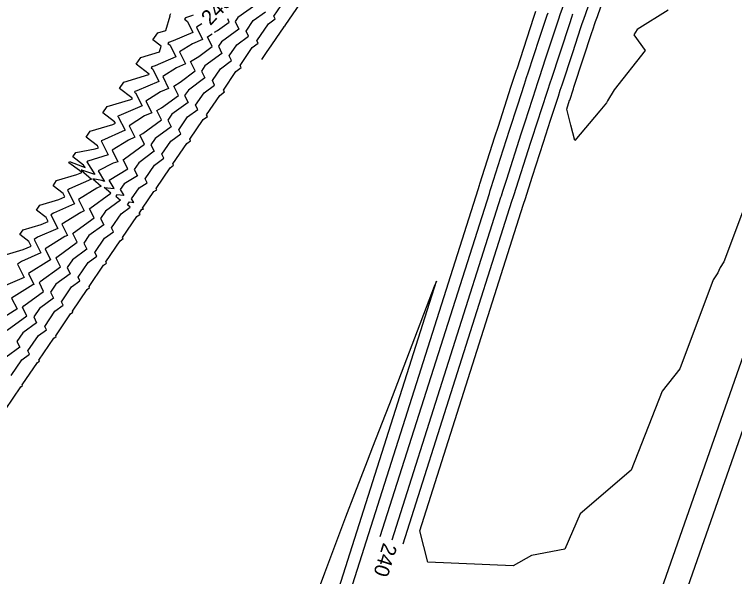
# Model space of a CAD drawing. Extents: x 1160447 to 1162032, y 616022 to 618272.
# Drawn here: x 1160877.4 to 1160997.8, y 616560 to 616654 of the extents above; entities that cross this region are included whole.
import ezdxf

# ---------------------------------------------------------------- set-up
doc = ezdxf.new("R2010")
doc.units = 0
doc.layers.add('D_Contours_Major', color=7, linetype='Continuous')
doc.layers.add('D_Contours_Minor', color=7, linetype='Continuous')

msp = doc.modelspace()

# ---------------------------------------------------------------- linework, layer by layer
at = {"layer": 'D_Contours_Major'}
for points in [[(1160969.77, 616657.13), (1160968.64, 616653.87), (1160968.38, 616653.13), (1160966.19, 616646.45), (1160965.24, 616643.54), (1160964.79, 616642.17), (1160964.61, 616641.62), (1160962.76, 616635.91), (1160962.12, 616633.94), (1160959.69, 616626.37), (1160959.04, 616624.33), (1160958.79, 616623.55), (1160958.73, 616623.36), (1160940.52, 616566.06)], [(1160925.19, 616655.85), (1160922.62, 616652.09), (1160922.66, 616652.01), (1160922.48, 616651.88), (1160919.81, 616647.97), (1160919.82, 616647.94), (1160919.77, 616647.91), (1160918.73, 616646.39)], [(1160908.78, 616652.36), (1160907.88, 616651.81), (1160908.9, 616649.76), (1160907.23, 616649.04), (1160905.05, 616647.69), (1160906.06, 616645.68), (1160904.54, 616645.02), (1160902.22, 616643.57), (1160903.22, 616641.59), (1160901.86, 616641), (1160899.4, 616639.46), (1160900.39, 616637.5), (1160899.19, 616636.98), (1160896.59, 616635.34), (1160897.56, 616633.41), (1160896.52, 616632.95), (1160893.78, 616631.23), (1160894.74, 616629.31), (1160893.94, 616629.06), (1160891.42, 616627.78), (1160892.49, 616626.03), (1160892.04, 616626.18), (1160890.53, 616626.46), (1160891.93, 616625.21), (1160891.19, 616624.89), (1160888.17, 616623), (1160889.12, 616621.11), (1160888.52, 616620.85), (1160885.37, 616618.88), (1160886.3, 616617.01), (1160885.86, 616616.81), (1160882.56, 616614.76), (1160883.49, 616612.91), (1160883.18, 616612.77), (1160879.76, 616610.65), (1160880.69, 616608.8), (1160880.5, 616608.73), (1160876.97, 616606.53), (1160877.88, 616604.7), (1160877.82, 616604.68), (1160874.17, 616602.41)], [(1160974.68, 616514.45), (1161006.96, 616606.59), (1161007.29, 616607.53), (1161007.74, 616608.8), (1161010.59, 616616.88), (1161011.09, 616618.29), (1161013.25, 616624.34), (1161013.42, 616624.81), (1161013.92, 616626.21), (1161014.8, 616628.63), (1161017.28, 616635.52), (1161017.6, 616638.61), (1161019.75, 616644.29), (1161020.92, 616644.74), (1161021.22, 616647.76), (1161021.25, 616647.83)]]:
    msp.add_lwpolyline(points, dxfattribs=at)
at = {"layer": 'D_Contours_Minor'}
for points in [[(1160986.75, 616654.67), (1160981.58, 616651.45), (1160980.98, 616650.53), (1160982.88, 616647.91), (1160977.73, 616641.35), (1160976.62, 616639.49), (1160976.43, 616639.17), (1160975.29, 616637.82), (1160971.11, 616632.88), (1160970.47, 616635.41), (1160969.78, 616638.13), (1160970.26, 616639.61), (1160970.27, 616639.63), (1160970.89, 616641.53), (1160970.97, 616641.77), (1160974.03, 616651.1), (1160974.06, 616651.2), (1160974.6, 616652.75), (1160974.9, 616653.6), (1160977.33, 616660.61)], [(1160999.14, 616620.91), (1160996.06, 616612.6), (1160995.44, 616611.66), (1160995.37, 616611.55), (1160995.06, 616610.73), (1160994.29, 616609.56), (1160988.7, 616594.7), (1160985.72, 616590.96), (1160980.56, 616577.76), (1160972.01, 616570.44), (1160969.44, 616564.53), (1160963.9, 616563.5), (1160960.8, 616561.74), (1160946.57, 616562.38), (1160945.2, 616567.59), (1160962.51, 616622.05), (1160962.63, 616622.41), (1160962.82, 616623.01), (1160964.07, 616626.93), (1160965.89, 616632.61), (1160967.08, 616636.27), (1160968.38, 616640.28), (1160968.7, 616641.26), (1160969, 616642.2), (1160970.78, 616647.59), (1160972.15, 616651.77), (1160972.38, 616652.43), (1160972.62, 616653.13), (1160974.41, 616658.31)], [(1160875.95, 616587.9), (1160878.51, 616591.66), (1160878.81, 616591.88), (1160878.74, 616592.01), (1160881.27, 616595.74), (1160881.61, 616595.98), (1160881.53, 616596.12), (1160884.04, 616599.81), (1160884.41, 616600.08), (1160884.33, 616600.23), (1160886.81, 616603.88), (1160887.21, 616604.17), (1160887.12, 616604.34), (1160889.58, 616607.95), (1160890.01, 616608.27), (1160889.92, 616608.45), (1160892.35, 616612.03), (1160892.82, 616612.36), (1160892.72, 616612.56), (1160895.13, 616616.1), (1160895.62, 616616.46), (1160895.52, 616616.66), (1160897.91, 616620.17), (1160898.43, 616620.55), (1160898.27, 616620.69), (1160898.74, 616621.39), (1160898.99, 616621.37), (1160898.87, 616621.57), (1160900.76, 616624.34), (1160901.24, 616624.64), (1160901.12, 616624.87), (1160903.47, 616628.3), (1160904.05, 616628.73), (1160903.93, 616628.97), (1160906.25, 616632.35), (1160906.87, 616632.81), (1160906.74, 616633.08), (1160909.01, 616636.39), (1160909.7, 616636.9), (1160909.55, 616637.18), (1160911.76, 616640.41), (1160912.53, 616640.98), (1160912.37, 616641.3), (1160914.47, 616644.4), (1160915.36, 616645.05), (1160915.17, 616645.43), (1160917.19, 616648.4), (1160918.2, 616649.12), (1160917.99, 616649.56), (1160919.92, 616652.39), (1160921.05, 616653.19), (1160920.81, 616653.68), (1160922.66, 616656.39)], [(1160917.82, 616655.55), (1160914.81, 616653.42), (1160914.35, 616652.74), (1160914.97, 616651.48), (1160912.04, 616649.38), (1160911.53, 616648.62), (1160912.13, 616647.41), (1160909.28, 616645.34), (1160908.71, 616644.49), (1160909.29, 616643.33), (1160906.52, 616641.3), (1160905.89, 616640.38), (1160906.46, 616639.24), (1160903.75, 616637.26), (1160903.07, 616636.27), (1160903.63, 616635.16), (1160900.98, 616633.22), (1160900.26, 616632.16), (1160900.81, 616631.07), (1160898.21, 616629.16), (1160897.45, 616628.05), (1160897.99, 616626.98), (1160895.78, 616625.6), (1160895.14, 616624.67), (1160895.74, 616623.7), (1160894.56, 616623.81), (1160894.4, 616623.58), (1160895.18, 616622.88), (1160892.67, 616621.05), (1160891.84, 616619.83), (1160892.37, 616618.78), (1160889.9, 616616.98), (1160889.04, 616615.72), (1160889.56, 616614.69), (1160887.13, 616612.91), (1160886.24, 616611.61), (1160886.75, 616610.59), (1160884.36, 616608.84), (1160883.44, 616607.49), (1160883.95, 616606.49), (1160881.6, 616604.77), (1160880.65, 616603.38), (1160881.14, 616602.39), (1160878.83, 616600.7), (1160877.85, 616599.26), (1160878.34, 616598.29), (1160876.06, 616596.63)], [(1160907.3, 616653.81), (1160907.02, 616653.69), (1160906.05, 616653.4), (1160905.88, 616653.15), (1160906.36, 616652.78), (1160907.28, 616650.94), (1160903.98, 616649.51), (1160903.22, 616649.28), (1160903.08, 616649.09), (1160903.46, 616648.8), (1160904.44, 616646.85), (1160900.95, 616645.33), (1160900.39, 616645.17), (1160900.29, 616645.03), (1160900.57, 616644.81), (1160901.6, 616642.76), (1160897.92, 616641.16), (1160897.57, 616641.05), (1160897.51, 616640.96), (1160897.68, 616640.83), (1160898.77, 616638.67), (1160894.91, 616636.98), (1160894.75, 616636.94), (1160894.72, 616636.9), (1160894.8, 616636.84), (1160895.94, 616634.58), (1160891.97, 616632.84), (1160891.94, 616632.82), (1160893.12, 616630.48), (1160889.69, 616629.39), (1160889.56, 616629.33), (1160890.87, 616627.2), (1160888.69, 616627.89), (1160888.59, 616627.91), (1160890.3, 616626.38), (1160886.64, 616624.78), (1160886.33, 616624.58), (1160887.49, 616622.28), (1160883.97, 616620.74), (1160883.53, 616620.46), (1160884.68, 616618.17), (1160881.29, 616616.7), (1160880.73, 616616.34), (1160881.87, 616614.07), (1160878.62, 616612.65), (1160877.93, 616612.22), (1160879.05, 616609.96), (1160875.93, 616608.6)], [(1160876.09, 616613.8), (1160878.9, 616614.64), (1160880.24, 616615.23), (1160879.86, 616615.99), (1160878.35, 616617.13), (1160878.89, 616617.92), (1160881.88, 616618.82), (1160883.05, 616619.33), (1160882.72, 616620), (1160881.12, 616621.21), (1160881.69, 616622.05), (1160884.86, 616623), (1160885.86, 616623.44), (1160885.58, 616624.01), (1160883.9, 616625.29), (1160884.49, 616626.17), (1160887.86, 616627.19), (1160888.68, 616627.54), (1160888.33, 616627.85), (1160886.53, 616629.16), (1160886.65, 616629.35), (1160888.8, 616628.5), (1160889.24, 616628.37), (1160888.99, 616628.77), (1160887.19, 616630.13), (1160887.7, 616630.88), (1160890.93, 616631.47), (1160891.5, 616631.65), (1160891.32, 616632), (1160889.44, 616633.44), (1160890.1, 616634.41), (1160893.87, 616635.55), (1160894.32, 616635.75), (1160894.19, 616636), (1160892.22, 616637.52), (1160892.92, 616638.53), (1160896.89, 616639.73), (1160897.15, 616639.84), (1160897.08, 616639.99), (1160895.01, 616641.59), (1160895.73, 616642.65), (1160899.91, 616643.91), (1160899.98, 616643.94), (1160899.96, 616643.98), (1160897.79, 616645.65), (1160898.56, 616646.76), (1160901.69, 616647.71), (1160901.97, 616648.65), (1160900.59, 616649.72), (1160901.39, 616650.88), (1160902.76, 616651.29), (1160903.48, 616653.7), (1160903.39, 616653.78), (1160903.6, 616654.08)], [(1160876.9, 616593.58), (1160878.67, 616596.18), (1160879.97, 616597.13), (1160879.69, 616597.69), (1160881.44, 616600.26), (1160882.77, 616601.23), (1160882.49, 616601.8), (1160884.2, 616604.33), (1160885.58, 616605.33), (1160885.28, 616605.92), (1160886.97, 616608.4), (1160888.38, 616609.43), (1160888.08, 616610.03), (1160889.74, 616612.47), (1160891.19, 616613.52), (1160890.88, 616614.14), (1160892.52, 616616.54), (1160894, 616617.62), (1160893.68, 616618.25), (1160895.29, 616620.61), (1160896.8, 616621.72), (1160896.33, 616622.14), (1160896.65, 616622.6), (1160897.37, 616622.53), (1160897, 616623.12), (1160898.27, 616624.97), (1160899.62, 616625.81), (1160899.29, 616626.46), (1160900.84, 616628.73), (1160902.43, 616629.9), (1160902.1, 616630.57), (1160903.61, 616632.78), (1160905.25, 616633.99), (1160904.91, 616634.67), (1160906.38, 616636.83), (1160908.08, 616638.07), (1160907.72, 616638.78), (1160909.14, 616640.86), (1160910.91, 616642.15), (1160910.54, 616642.9), (1160911.87, 616644.87), (1160913.75, 616646.23), (1160913.35, 616647.03), (1160914.62, 616648.89), (1160916.59, 616650.3), (1160916.17, 616651.15), (1160917.37, 616652.91), (1160919.43, 616654.37)], [(1160914.15, 616496.3), (1160954.95, 616624.67), (1160955.2, 616625.43), (1160955.26, 616625.64), (1160957.77, 616633.46), (1160958.35, 616635.27), (1160960.46, 616641.78), (1160960.84, 616642.96), (1160961.38, 616644.61), (1160961.47, 616644.88), (1160964.29, 616653.47), (1160964.62, 616654.48)], [(1160938.61, 616566.66), (1160956.84, 616624.02), (1160957, 616624.49), (1160957.15, 616624.99), (1160958.73, 616629.91), (1160960.23, 616634.6), (1160961.61, 616638.84), (1160962.72, 616642.29), (1160963.08, 616643.39), (1160963.35, 616644.21), (1160965.24, 616649.96), (1160966.5, 616653.81), (1160966.65, 616654.24)], [(1160942.42, 616565.45), (1160960.62, 616622.7), (1160960.89, 616623.53), (1160960.93, 616623.67), (1160963.79, 616632.61), (1160964.01, 616633.27), (1160966.49, 616640.93), (1160966.49, 616640.95), (1160967.12, 616642.87), (1160967.15, 616642.95), (1160970.27, 616652.45), (1160970.63, 616653.5), (1160970.81, 616654.03)], [(1160910.91, 616650.96), (1160911.39, 616651.25), (1160913.36, 616652.66), (1160913.09, 616653.19)], [(1160876.22, 616601.15), (1160879.51, 616603.54), (1160878.81, 616604.95), (1160878.99, 616605.22), (1160882.32, 616607.65), (1160881.6, 616609.07), (1160881.75, 616609.29), (1160885.12, 616611.75), (1160884.4, 616613.19), (1160884.52, 616613.36), (1160887.93, 616615.85), (1160887.2, 616617.3), (1160887.29, 616617.42), (1160890.74, 616619.95), (1160890, 616621.42), (1160890.05, 616621.48), (1160893.55, 616624.05), (1160892.46, 616625.02), (1160892.46, 616625.02), (1160894.12, 616624.87), (1160893.28, 616626.23), (1160893.28, 616626.23), (1160896.37, 616628.14), (1160895.61, 616629.64), (1160895.84, 616629.78), (1160899.19, 616632.24), (1160898.42, 616633.75), (1160898.92, 616634.06), (1160902.01, 616636.33), (1160901.24, 616637.86), (1160902.02, 616638.35), (1160904.84, 616640.42), (1160904.06, 616641.97), (1160905.13, 616642.64), (1160907.67, 616644.5), (1160906.88, 616646.09), (1160908.25, 616646.94), (1160910.51, 616648.58), (1160909.7, 616650.21), (1160910.49, 616650.7)], [(1160912.26, 616496.96), (1160947.99, 616609.37), (1160947.64, 616608.46), (1160947.19, 616607.27), (1160940.15, 616588.84), (1160940.05, 616588.57), (1160937.33, 616581.57), (1160936.43, 616579.25), (1160934.32, 616573.8), (1160932.81, 616569.92), (1160929.29, 616560.55), (1160921.49, 616539.57)], [(1160958.66, 616480.83), (1161003.19, 616607.91)]]:
    msp.add_lwpolyline(points, dxfattribs=at)

# ---------------------------------------------------------------- texts
at = {"layer": 'D_Contours_Major'}
for s, rotation, p in [('245', 45.7543, (1160910.18, 616651.99)), ('240', 252.3666, (1160939.11, 616565.73))]:
    msp.add_text(s, height=2.49, rotation=rotation, dxfattribs=at).set_placement(p)

doc.saveas('drawing.dxf')
